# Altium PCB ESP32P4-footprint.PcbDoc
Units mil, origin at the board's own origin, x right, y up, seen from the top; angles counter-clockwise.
Board outline 2834.55 x 2047.04 mil, 2 copper layers (Top Layer, Bottom Layer), stack 65.398 mil thick; 35 components, 0 nets, 396 pads, 0 vias.
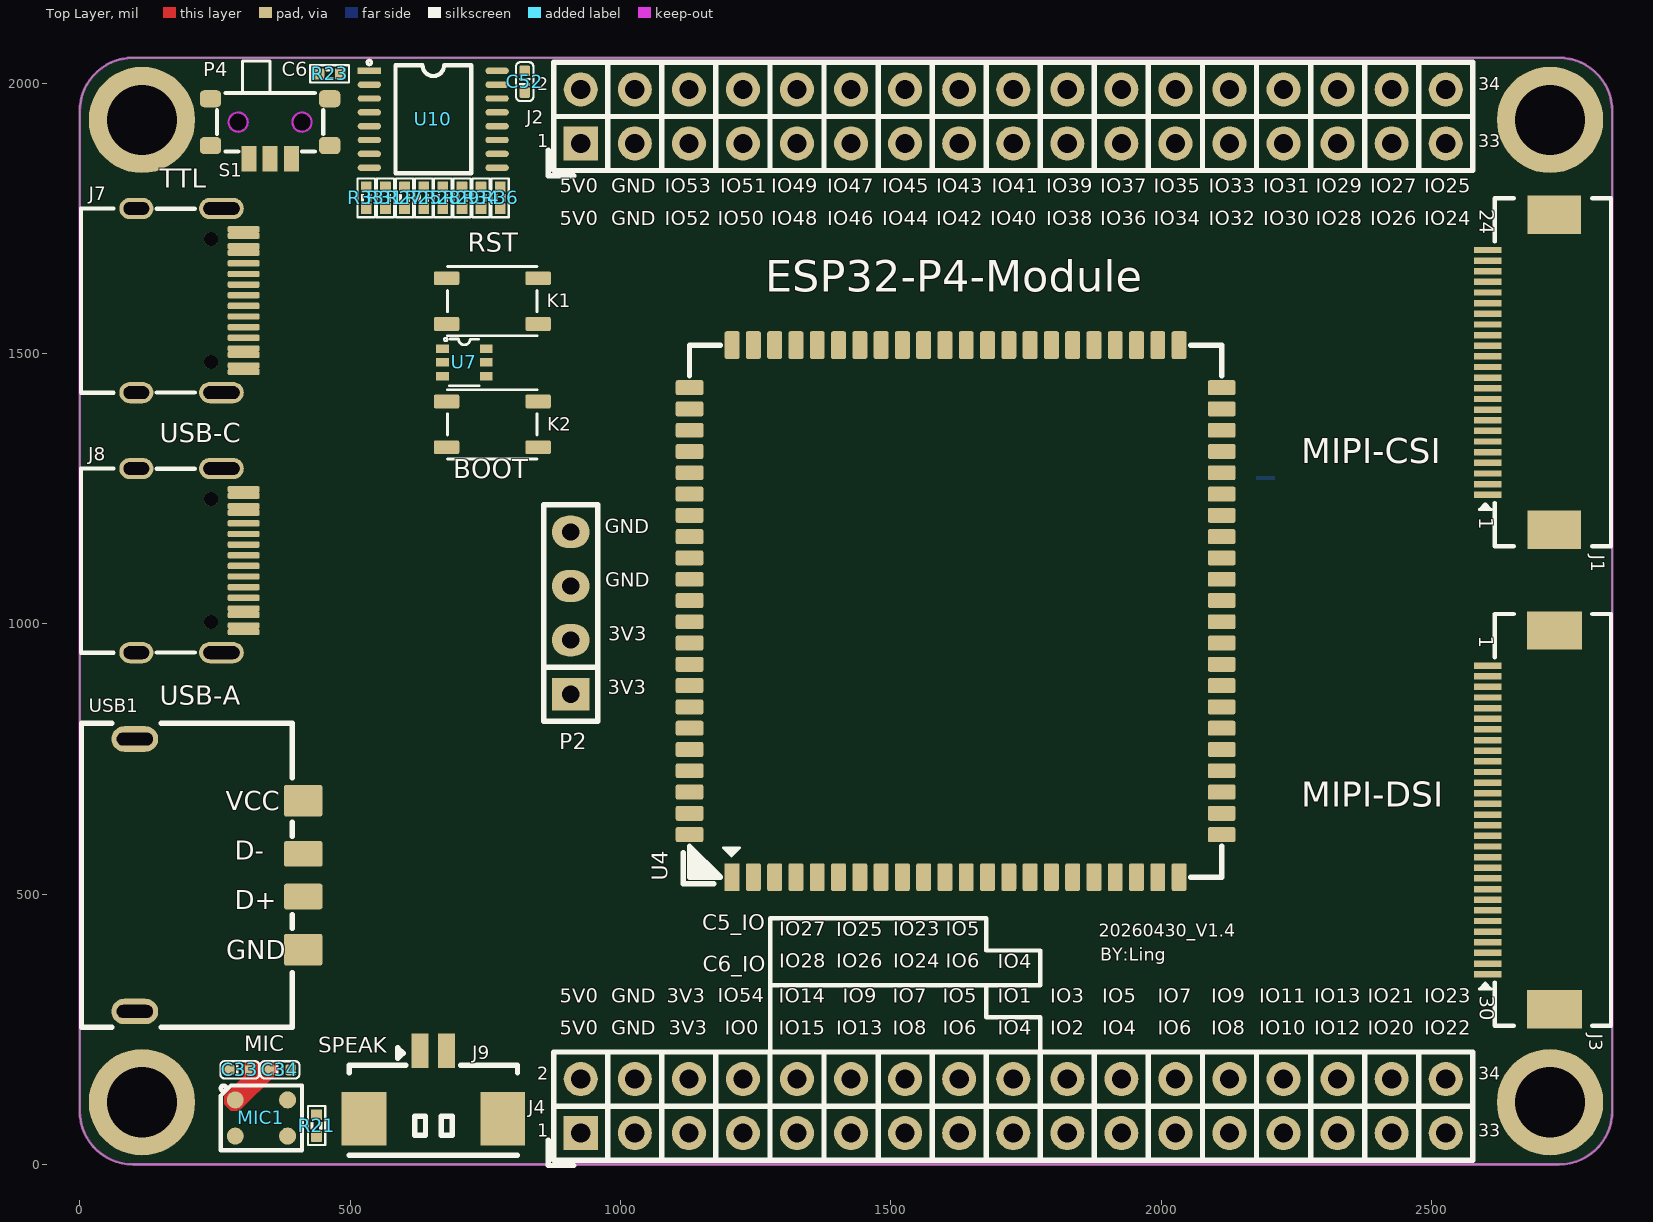
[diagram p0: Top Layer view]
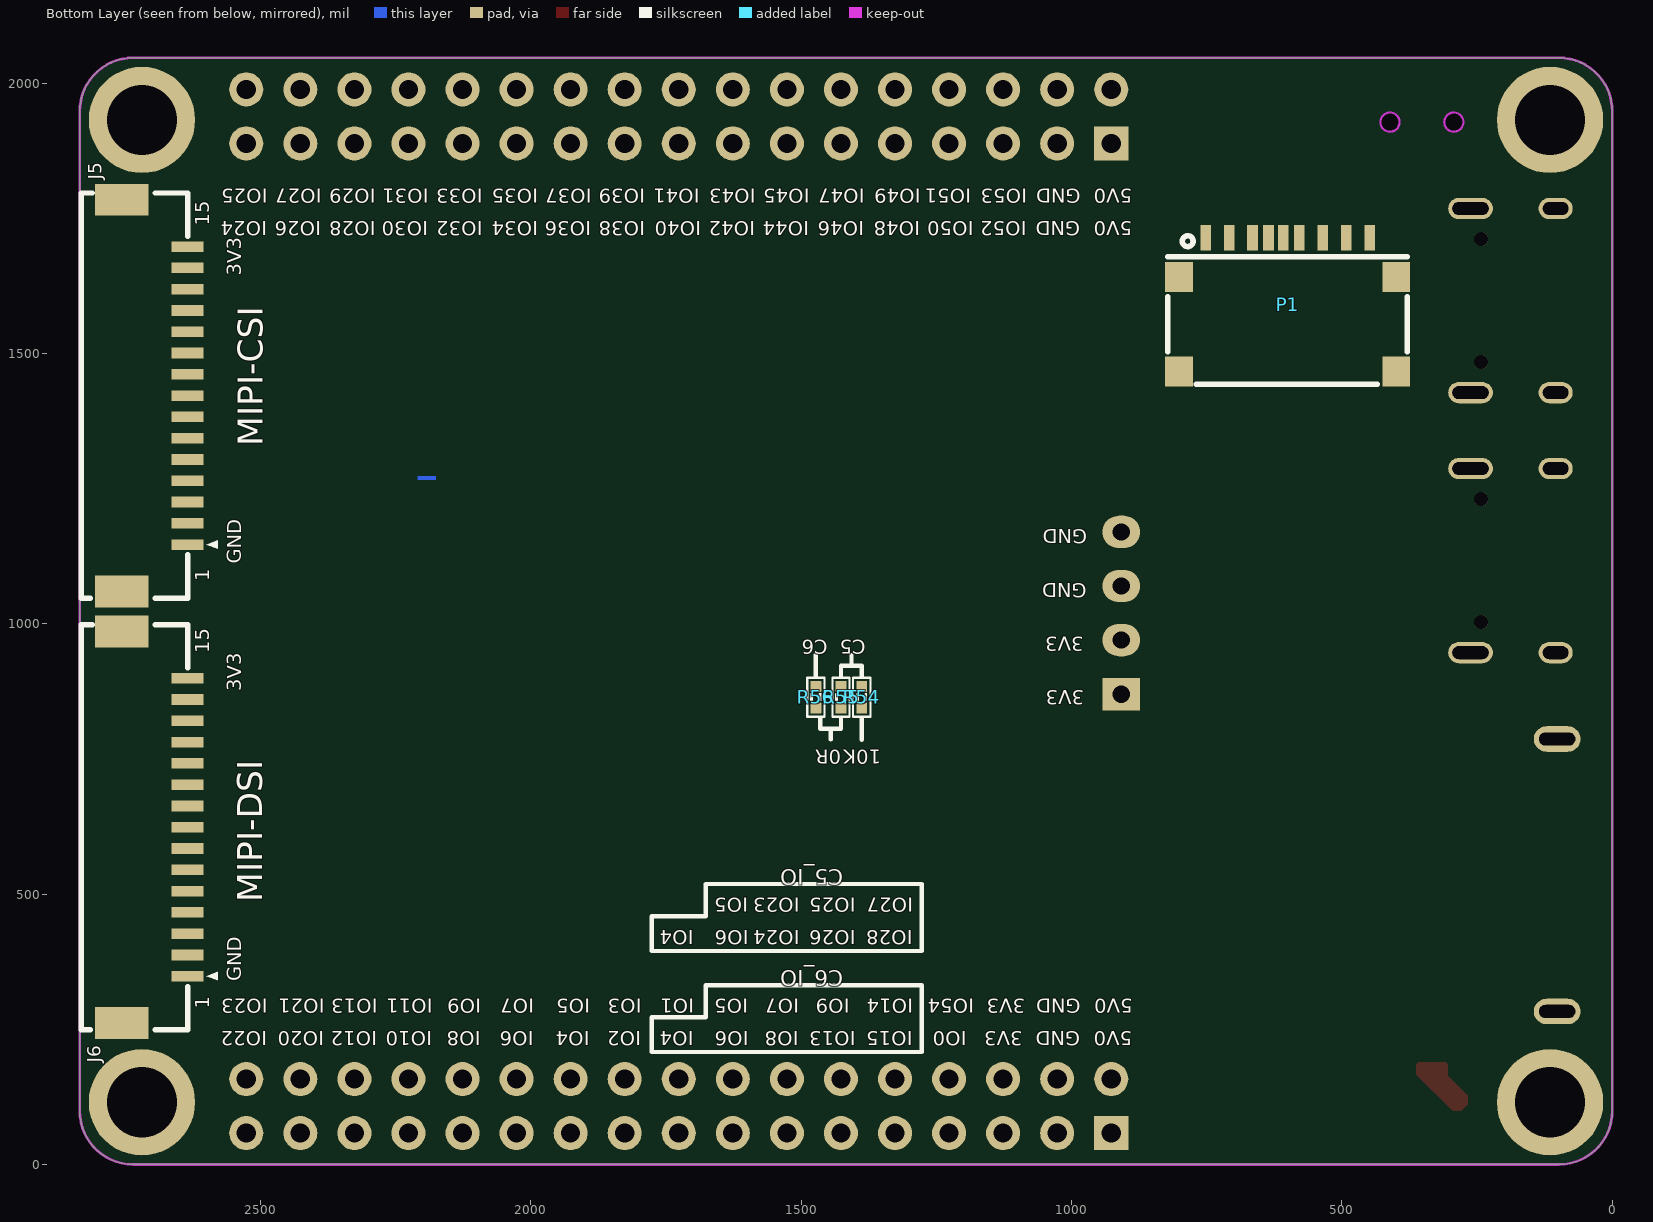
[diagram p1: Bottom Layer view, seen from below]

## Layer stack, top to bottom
Top Solder: solder mask 0.4, Solder Resist, Dk 3.5
Top Layer: signal copper 1.4
Dielectric 1: dielectric 62.5984, FR-4, Dk 4.8
Bottom Layer: signal copper 1.4
Bottom Solder: solder mask 0.4, Solder Resist, Dk 3.5

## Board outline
0,98.43 0,1948.61 cw(c98.42,1948.61) 98.43,2047.04 2736.12,2047.04 cw(c2736.12,1948.61) 2834.55,1948.61 2834.55,98.43 cw(c2736.12,98.43) 2736.12,0 98.43,0 cw(c98.42,98.43)

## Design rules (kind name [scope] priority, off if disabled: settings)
Clearance Clearance_1 [InNamedPolygon('NONET_L-01_P-001') vs InComponent('U4')] p1: gap=6 ignorepadtopadclearanceinfootprint=TRUE except(0: Arc-Hole Track-Hole SMDPad-Hole THPad-Hole Via-Hole Fill-Hole Poly-Hole Region-Hole Text-Hole; 10: SMDPad-Poly)
Clearance [All] p2: gap=6 ignorepadtopadclearanceinfootprint=TRUE except(0: Arc-Hole Track-Hole SMDPad-Hole THPad-Hole Via-Hole Fill-Hole Poly-Hole Region-Hole Text-Hole; 8: THPad-Poly)
ComponentClearance [All] p1: gap=0 collisioncheckmode=3 verticalgap=0 showdistances=FALSE
DiffPairsRouting DIFF100 [All] p1: maxlimit=6 minlimit=6 mostfreqgap=6 toplayer_minwidth=7.4 toplayer_maxwidth=7.4 toplayer_prefwidth=7.4 bottomlayer_minwidth=7.4 bottomlayer_maxwidth=7.4 bottomlayer_prefwidth=7.4 maxuncoupledlength=500
HoleSize [All] p1: absolutevalues=TRUE maxlimit=500 minlimit=1 maxpercent=80.000 minpercent=20.000
HoleToHoleClearance [All] p1: gap=4 allowstackedmicrovias=TRUE
MatchedLengths 15P_DSI [InxSignalClass('15P_DSI')] p1: tolerance=10 checknetsindiffpair=FALSE checkdiffpairvsdiffpair=TRUE checkxsignals=TRUE checkothers=TRUE
MatchedLengths 15P_CSI [InxSignalClass('15P_CSI')] p2: tolerance=10 checknetsindiffpair=FALSE checkdiffpairvsdiffpair=TRUE checkxsignals=TRUE checkothers=TRUE
MatchedLengths DSI [InxSignalClass('DSI')] p3: tolerance=10 checknetsindiffpair=FALSE checkdiffpairvsdiffpair=TRUE checkxsignals=TRUE checkothers=TRUE
MatchedLengths CSI [InxSignalClass('CSI')] p4: tolerance=10 checknetsindiffpair=FALSE checkdiffpairvsdiffpair=TRUE checkxsignals=TRUE checkothers=TRUE
MinimumSolderMaskSliver [All] p1: minsoldermaskwidth=0
PlaneConnect [All] p1: pad.planeconnectstyle=Relief pad.reliefexpansion=20 pad.reliefentries=4 pad.reliefconductorwidth=10 pad.reliefairgap=10 via.planeconnectstyle=Direct via.reliefexpansion=20 via.reliefentries=4 via.reliefconductorwidth=10 via.reliefairgap=10
PolygonConnect [All] p1: thpad.connectstyle=Relief thpad.reliefconductorwidth=15 thpad.reliefentries=4 thpad.polygonreliefangle="90 Angle" thpad.airgapwidth=8 smdpad.connectstyle=Direct smdpad.reliefconductorwidth=15 smdpad.reliefentries=4 smdpad.polygonreliefangle="90 Angle" smdpad.airgapwidth=8 via.connectstyle=Direct via.reliefconductorwidth=10 via.reliefentries=4 via.polygonreliefangle="90 Angle" via.airgapwidth=10
RoutingVias [All] p1: holewidth=28 width=50 viastyle="Through Hole" minholewidth=11 minwidth=18 maxholewidth=28 maxwidth=50
SilkToSilkClearance [All] p1: silktosilkclearance=0
SilkToSolderMaskClearance [IsPad] p1: minsilkscreentomaskgap=0 clearancetoexposedcopper=TRUE
SolderMaskExpansion [All] p1: expansion=4 istentingtop=FALSE
Width [All] p1: maxlimit=50 minlimit=6 preferedwidth=6
22 further rules are at their usual default settings.

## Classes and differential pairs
differential pair USBuart: +USBuart_P -USBuart_N
differential pair USBIN: +USBIN_P -USBIN_N
differential pair USB_D: +USB_D_P -USB_D_N
differential pair USB_A: +USB_A_P -USB_A_N
differential pair DSI_D1: +DSI_D1_P -DSI_D1_N
differential pair DSI_D0: +DSI_D0_P -DSI_D0_N
differential pair DSI_CLK: +DSI_CLK_P -DSI_CLK_N
differential pair CSI_D1: +CSI_D1_P -CSI_D1_N
differential pair CSI_D0: +CSI_D0_P -CSI_D0_N
differential pair CSI_CLK: +CSI_CLK_P -CSI_CLK_N

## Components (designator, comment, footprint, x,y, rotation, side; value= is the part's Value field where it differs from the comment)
C33 "1uF" "CAP_0402 - G" 296,175 r180 top
C34 "0.1uF" "CAP_0402 - G" 370.29,175 r0 top
C52 "0.1uF" "CAP_0402 - G" 823,2003 r270 top
J1 "SC2336" FPC0.5-24P 2702.5,1465.16 r90 top locked
J2 "2X17P排针2.54MM间距" HDR2.54-LI-2x17P 1726.63,1938.52 r0 top locked
J3 "YDP400BT001-V4" FPC0.5-30P 2702.5,637.36 r90 top locked
J4 "2X17P排针2.54MM间距" HDR2.54-LI-2x17P 1726.63,108.01 r0 top locked
J5 "FPC-1.0HF-15PWAR-H20" FPC-SMD_XUNPU_FPC-1.0HF-15PWAR-H20 2696.03,1422.2 r270 bottom locked
J6 "FPC-1.0HF-15PWAR-H20" FPC-SMD_XUNPU_FPC-1.0HF-15PWAR-H20 2696.03,623.78 r270 bottom locked
J7 "TYPEC-16P" TypeC-16P 203.8,1598 r0 top locked
J8 "TYPEC-16P" TypeC-16P 203.8,1117 r0 top locked
J9 "MX1.25-2P" "MX 1.25-LS-2P" 654,155 r0 top locked
K1 "Button-4P" SWITCH_3X4X2.5_4PIN_SMD 763,1597 r180 top
K2 "Button-4P" SWITCH_3X4X2.5_4PIN_SMD 763,1369 r180 top
MIC1 "LMA3729T421-OA1" MIC-SMD_4P-L3.8-W3.0-P2.46-S1.70-TR 336,86 r90 top
P1 "TF-123-ARP9H17" TF-SMD_TF-123-ARP9H15 600.38,1588.31 r0 bottom locked
P2 "1X4排针" "Pin HDR1X4/2.54mm-S" 908,870 r180 top
R21 "0R" "RES_0402 -G" 438,72 r90 top
R23 "10K" "RES_0402 -G" 462.26,2017.35 r180 top
R25 "0R" "RES_0402 -G" 636.08,1788 r90 top
R27 "0R" "RES_0402 -G" 600.71,1788 r90 top
R28 "0R" "RES_0402 -G" 671.45,1788 r270 top
R29 "0R" "RES_0402 -G" 706.82,1788 r270 top
R31 "0R" "RES_0402 -G" 565.34,1788 r90 top
R33 "0R" "RES_0402 -G" 529.97,1788 r270 top
R34 "0R" "RES_0402 -G" 742.19,1788 r270 top
R36 "0R" "RES_0402 -G" 777.56,1788 r270 top
R54 "10K" "RES_0402 -G" 1388,864.22 r90 bottom
R55 "0R" "RES_0402 -G" 1426.46,864.22 r270 bottom
R56 "0R" "RES_0402 -G" 1473,864.22 r270 bottom
S1 "SS-205-AGS7P-150" SS-205-AGS7P-150 352,1928 r180 top
U4 "ESP32-P4C6/C5_Module" ESP32P4模组封装 1620,1023.52 r90 top locked
U7 "DDC114TU-7-F/UMH3N" SC70 711.37,1483.47 r0 top
U10 "RS2233XTSS16-Q1" TSSOP16_N 653.92,1933.35 r0 top
USB1 "10.0 QCHTZB5.7" USB-A-SMD_10.0-QCHTZB5.7 250,535 r0 top locked

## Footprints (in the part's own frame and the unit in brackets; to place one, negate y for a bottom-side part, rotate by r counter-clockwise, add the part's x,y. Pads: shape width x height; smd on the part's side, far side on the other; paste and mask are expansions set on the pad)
"CAP_0402 - G" [mil]
  rrect35% 20x20 smd mask+2: 1(-20,0) 2(20,0)
  silkscreen extent -36,-16 36,16, body extent -20,-10 20,10, height 20
ESP32P4模组封装 [mm]
  rect 1.3x0.7 smd mask+0.051: 1(-12.5,10.5)
  rrect25% 1.3x0.7 smd mask+0.051: 2(-12.5,9.5) 3(-12.5,8.5) 4(-12.5,7.5) 5(-12.5,6.5) 6(-12.5,5.5) 7(-12.5,4.5) 8(-12.5,3.5) 9(-12.5,2.5) 10(-12.5,1.5) 11(-12.5,0.5) 12(-12.5,-0.5) 13(-12.5,-1.5) 14(-12.5,-2.5) 15(-12.5,-3.5) 16(-12.5,-4.5) 17(-12.5,-5.5) 18(-12.5,-6.5) 19(-12.5,-7.5) 20(-12.5,-8.5) 21(-12.5,-9.5) 22(-12.5,-10.5) 45(12.5,-10.5) 46(12.5,-9.5) 47(12.5,-8.5) 48(12.5,-7.5) 49(12.5,-6.5) 50(12.5,-5.5) 51(12.5,-4.5) 52(12.5,-3.5) 53(12.5,-2.5) 54(12.5,-1.5) 55(12.5,-0.5) 56(12.5,0.5) 57(12.5,1.5) 58(12.5,2.5) 59(12.5,3.5) 60(12.5,4.5) 61(12.5,5.5) 62(12.5,6.5) 63(12.5,7.5) 64(12.5,8.5) 65(12.5,9.5) 66(12.5,10.5)
  rrect25% 0.7x1.3 smd mask+0.051: 23(-10.5,-12.5) 24(-9.5,-12.5) 25(-8.5,-12.5) 26(-7.5,-12.5) 27(-6.5,-12.5) 28(-5.5,-12.5) 29(-4.5,-12.5) 30(-3.5,-12.5) 31(-2.5,-12.5) 32(-1.5,-12.5) 33(-0.5,-12.5) 34(0.5,-12.5) 35(1.5,-12.5) 36(2.5,-12.5) 37(3.5,-12.5) 38(4.5,-12.5) 39(5.5,-12.5) 40(6.5,-12.5) 41(7.5,-12.5) 42(8.5,-12.5) 43(9.5,-12.5) 44(10.5,-12.5) 67(10.5,12.5) 68(9.5,12.5) 69(8.5,12.5) 70(7.5,12.5) 71(6.5,12.5) 72(5.5,12.5) 73(4.5,12.5) 74(3.5,12.5) 75(2.5,12.5) 76(1.5,12.5) 77(0.5,12.5) 78(-0.5,12.5) 79(-1.5,12.5) 80(-2.5,12.5) 81(-3.5,12.5) 82(-4.5,12.5) 83(-5.5,12.5) 84(-6.5,12.5) 85(-7.5,12.5) 86(-8.5,12.5) 87(-9.5,12.5) 88(-10.5,12.5)
  silkscreen extent -12.8,-12.5 12.5,12.8, body extent -12.51,-12.51 12.5,12.5, height 3.25
FPC0.5-24P [mm]
  rect 1.8x2.5 smd: 0(-7.4,-0.635) 0(7.4,-0.635)
  rect 0.3x1.3 smd: 1(-5.75,2.497) 2(-5.25,2.497) 3(-4.75,2.497) 4(-4.25,2.497) 5(-3.75,2.497) 6(-3.25,2.497) 7(-2.75,2.497) 8(-2.25,2.497) 9(-1.75,2.497) 10(-1.25,2.497) 11(-0.75,2.497) 12(-0.25,2.497) 13(0.25,2.497) 14(0.75,2.497) 15(1.25,2.497) 16(1.75,2.497) 17(2.25,2.497) 18(2.75,2.497) 19(3.25,2.497) 20(3.75,2.497) 21(4.25,2.497) 22(4.75,2.497) 23(5.25,2.497) 24(5.75,2.497)
  silkscreen extent -8.18,-3.3 8.18,2.89, body extent -8.1,-3.25 8.1,2.75, height 2
FPC0.5-30P [mm]
  rect 1.8x2.58 smd: 0(-8.9,-0.635) 0(8.9,-0.635)
  rect 0.3x1.3 smd: 1(-7.25,2.497) 2(-6.75,2.497) 3(-6.25,2.497) 4(-5.75,2.497) 5(-5.25,2.497) 6(-4.75,2.497) 7(-4.25,2.497) 8(-3.75,2.497) 9(-3.25,2.497) 10(-2.75,2.497) 11(-2.25,2.497) 12(-1.75,2.497) 13(-1.25,2.497) 14(-0.75,2.497) 15(-0.25,2.497) 16(0.25,2.497) 17(0.75,2.497) 18(1.25,2.497) 19(1.75,2.497) 20(2.25,2.497) 21(2.75,2.497) 22(3.25,2.497) 23(3.75,2.497) 24(4.25,2.497) 25(4.75,2.497) 26(5.25,2.497) 27(5.75,2.497) 28(6.25,2.497) 29(6.75,2.497) 30(7.25,2.497)
  silkscreen extent -9.68,-3.3 9.67,2.89, body extent -9.6,-3.2 9.6,2.8, height 2
FPC-SMD_XUNPU_FPC-1.0HF-15PWAR-H20 [mm]
  rect 1.5x2.5 smd paste+0 mask+0.051: 0(-9.2,-1.55) 0(9.2,-1.55)
  rect 0.5x1.5 smd paste+0 mask+0.051: 1(7,1.55) 2(6,1.55) 3(5,1.55) 4(4,1.55) 5(3,1.55) 6(2,1.55) 7(1,1.55) 8(0,1.55) 9(-1,1.55) 10(-2,1.55) 11(-3,1.55) 12(-4,1.55) 13(-5,1.55) 14(-6,1.55) 15(-7,1.55)
  silkscreen extent -9.52,-3.45 9.52,2.97, body extent -9.54,-3.45 9.54,2.45, height 2.02
HDR2.54-LI-2x17P [mm] "双排排针，17x2脚"
  rect 1.6x1.6 hole 0.9: 1(-20.32,-1.27)
  round 1.6 hole 0.9: 2(-20.32,1.27) 3(-17.78,-1.27) 4(-17.78,1.27) 5(-15.24,-1.27) 6(-15.24,1.27) 7(-12.7,-1.27) 8(-12.7,1.27) 9(-10.16,-1.27) 10(-10.16,1.27) 11(-7.62,-1.27) 12(-7.62,1.27) 13(-5.08,-1.27) 14(-5.08,1.27) 15(-2.54,-1.27) 16(-2.54,1.27) 17(0,-1.27) 18(0,1.27) 19(2.54,-1.27) 20(2.54,1.27) 21(5.08,-1.27) 22(5.08,1.27) 23(7.62,-1.27) 24(7.62,1.27) 25(10.16,-1.27) 26(10.16,1.27) 27(12.7,-1.27) 28(12.7,1.27) 29(15.24,-1.27) 30(15.24,1.27) 31(17.78,-1.27) 32(17.78,1.27) 33(20.32,-1.27) 34(20.32,1.27)
  silkscreen extent -21.84,-2.79 21.59,2.54, body extent -21.59,-2.54 21.59,2.54, height 8.5
MIC-SMD_4P-L3.8-W3.0-P2.46-S1.70-TR [mm]
  round 0.8 smd mask+0.051: 1(0.85,1.23) 2(0.85,-1.23) 3(-0.85,-1.23) 4(-0.85,1.23)
  silkscreen extent -1.52,-1.91 1.52,1.9, body extent -1.5,-2 1.5,2, height 0.97
"MX 1.25-LS-2P" [mm] "长：7.25m，宽：3.7mm，高：4.7mm"
  rect 2.1x2.5 smd: 0(-3.255,-1.786) 0(3.255,-1.786)
  rect 0.8x1.6 smd: 1(-0.625,1.405) 2(0.625,1.405)
  silkscreen extent -3.95,-3.51 3.95,1.55, body extent -3.75,-3.51 3.75,1.74, height 3.62
"Pin HDR1X4/2.54mm-S" [mil]
  rect 70x60 hole 32: 1(0,0)
  oval 70x60 hole 32: 2(0,-100) 3(0,-200) 4(0,-300)
  silkscreen extent -50,-350 50,50, body extent -50,-350 50,50, height 336
"RES_0402 -G" [mil]
  rrect10% 20x20 smd mask+2: 1(-20,0) 2(20,0)
  silkscreen extent -36,-16 36,16, body extent -20,-10 20,10, height 14
SC70 [mm]
  rect 0.6x0.4 smd mask+0.025: 1(-1.026,0.65) 2(-1.026,0) 3(-1.026,-0.65) 4(1.026,-0.65) 5(1.026,0) 6(1.026,0.65)
  silkscreen extent -0.95,-1.1 0.7,1.16, body extent -1.2,-1.07 1.2,1.07, height 1.08
SS-205-AGS7P-150 [mm]
  rrect50% 1x0.8 smd mask+0.051: 0(-2.8,-1.1) 0(-2.8,1.1) 0(2.8,-1.1) 0(2.8,1.1)
  rect 0.7x1.2 smd mask+0.051: 1(-1,1.711) 2(0,1.711) 3(1,1.711)
  Keep-Out Layer board cut-out: 1.05,0 1.084,-0.172 1.182,-0.318 1.328,-0.416 1.5,-0.45 1.5,-0.45 1.672,-0.416 1.818,-0.318 1.916,-0.172 1.95,0 1.95,0 1.916,0.172 1.818,0.318 1.672,0.416 1.5,0.45 1.5,0.45 1.328,0.416 1.182,0.318 1.084,0.172 1.05,0
  Keep-Out Layer board cut-out: -1.5,-0.45 -1.672,-0.416 -1.818,-0.318 -1.916,-0.172 -1.95,0 -1.95,0 -1.916,0.172 -1.818,0.318 -1.672,0.416 -1.5,0.45 -1.5,0.45 -1.328,0.416 -1.182,0.318 -1.084,0.172 -1.05,0 -1.05,0 -1.084,-0.172 -1.182,-0.318 -1.328,-0.416 -1.5,-0.45
  Keep-Out Layer circle w0.1: c1.5,0 r0.45
  Keep-Out Layer circle w0.1: c-1.5,0 r0.45
  silkscreen extent -2.5,-2.88 2.5,1.37, body extent -3,-2.82 3,2.18, height 1.38
SWITCH_3X4X2.5_4PIN_SMD [mm]
  rrect25% 1.2x0.65 smd: 1(-2.15,1.075) 2(2.15,1.075) 3(-2.15,-1.075) 4(2.15,-1.075)
  silkscreen extent -2.1,-1.63 2.1,1.63, body extent -2.55,-1.57 2.55,1.57, height 2.5
TF-SMD_TF-123-ARP9H15 [mm]
  rect 1.3x1.4 smd: 0(-5.1,3.092) 0(-5.1,-1.357) 0(5.1,-1.357) 0(5.1,3.092)
  rect 0.5x1.2 smd: 1(3.85,-3.192) 2(2.75,-3.192) 3(1.65,-3.192) 4(0.9,-3.192) 5(-0.55,-3.192) 6(-1.65,-3.192) 7(-2.75,-3.192) 8(-3.85,-3.192) 9(0.2,-3.192)
  silkscreen extent -5.62,-3.29 5.62,3.69, body extent -5.63,-3.41 5.62,3.69, height 1.5
TSSOP16_N [mm] "5*6.4*1mm（长宽高）"
  rect 1.1x0.3 smd mask+0.051: 1(-3.004,2.275)
  oval 1.1x0.3 smd mask+0.051: 2(-3.004,1.625) 3(-3.004,0.975) 4(-3.004,0.325) 5(-3.004,-0.325) 6(-3.004,-0.975) 7(-3.004,-1.625) 8(-3.004,-2.275) 9(2.996,-2.275) 10(2.996,-1.625) 11(2.996,-0.975) 12(2.996,-0.325) 13(2.996,0.325) 14(2.996,0.975) 15(2.996,1.625) 16(2.996,2.275)
  silkscreen extent -3.11,-2.54 1.78,2.77, body extent -3.2,-2.5 3.2,2.5, height 1.03
TypeC-16P [mm]
  round 0.65 hole 0.65: 0(0.98,-2.89) 0(0.98,2.89)
  oval 1.6x1 hole 0.6 slot 1.2 at 0 deg: 1(-2.52,-4.325) 2(-2.52,4.325)
  oval 2.1x1 hole 0.6 slot 1.7 at 0 deg: 3(1.48,4.325) 4(1.48,-4.325)
  rrect50% 1.5x0.3 smd mask+0.051: A1(2.52,3.35) A4(2.52,2.55) A5(2.52,1.25) A6(2.52,0.25) A7(2.52,-0.25) A8(2.52,-1.25) A9(2.52,-2.55) A12(2.52,-3.35) B1(2.52,-3.05) B4(2.52,-2.25) B5(2.52,-1.75) B6(2.52,-0.75) B7(2.52,0.75) B8(2.52,1.75) B9(2.52,2.25) B12(2.52,3.05)
  silkscreen extent -5.12,-4.33 0.22,4.33, body extent -5.18,-4.48 2.57,4.48, height 3.26
USB-A-SMD_10.0-QCHTZB5.7 [mm]
  rrect15% 1.8x1.5 smd paste+0 mask+0.102: 1(4.146,3.5) 4(4.146,-3.5)
  rrect15% 1.8x1.2 smd paste+0 mask+0.102: 2(4.146,1) 3(4.146,-1)
  oval 2.2x1.2 hole 0.61 slot 1.7 at 0 deg: 5(-3.765,-6.4) 6(-3.765,6.4)
  silkscreen extent -6.27,-7.15 3.64,7.15, body extent -6.68,-7.15 4.32,7.15, height 5.8

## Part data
C33 C34 C52: library part CAP, "Capacitor"
J2 J4: library part "Pin HDR2X17"
J3: library part YDP210B001-V9
J5 J6: library part FPC0.5-15P, "贴片"
J7 J8: library part TYPEC-300A-BCP16H130, "16P立式直插TYPEC接口H=13MM，C5454932"
J9 P2: library part "Header 4", "Header, 4-Pin"
K1 K2: "Button"
MIC1: library part MSM381A3729H9CP
P1: "TF-123-ARP9H17,拔插式 MicroSD卡(TF卡) 卡座 短体9P中间侦测 1.7H"
R21 R23 R25 R27 R28 R29 R31 R33 R34 R36 R54 R55 R56: library part Res2, "Resistor"
S1: library part MSK-12C01-07
U4: library part ESP32-P4_Module
U7: library part HUMH9NTN
U10: "2:1(SPDT)4通道模拟开关"
USB1: library part USB-256-BRWH130, "USBA母座无卷边立式直插H=13.1MM，C720542"

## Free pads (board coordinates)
  round 196.85 hole 129.92 mask+0.98: 25(115,115) 25(115,1932.04) 25(2719.55,115) 25(2719.55,1932.04)

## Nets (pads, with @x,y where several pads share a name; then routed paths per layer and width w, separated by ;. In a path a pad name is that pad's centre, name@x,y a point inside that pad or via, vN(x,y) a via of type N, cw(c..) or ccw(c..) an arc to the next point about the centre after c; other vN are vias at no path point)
pads on no net: C33.1 C33.2 C34.1 C34.2 C52.1 C52.2 J1.0 J1.1 J1.2 J1.3 J1.4 J1.5 J1.6 J1.7 J1.8 J1.9 J1.10 J1.11 J1.12 J1.13 J1.14 J1.15 J1.16 J1.17 J1.18 J1.19 J1.20 J1.21 J1.22 J1.23 J1.24 J2.1 J2.2 J2.3 J2.4 J2.5 J2.6 J2.7 J2.8 J2.9 J2.10 J2.11 J2.12 J2.13 J2.14 J2.15 J2.16 J2.17 J2.18 J2.19 J2.20 J2.21 J2.22 J2.23 J2.24 J2.25 J2.26 J2.27 J2.28 J2.29 J2.30 J2.31 J2.32 J2.33 J2.34 J3.0 J3.1 J3.2 J3.3 J3.4 J3.5 J3.6 J3.7 J3.8 J3.9 J3.10 J3.11 J3.12 J3.13 J3.14 J3.15 J3.16 J3.17 J3.18 J3.19 J3.20 J3.21 J3.22 J3.23 J3.24 J3.25 J3.26 J3.27 J3.28 J3.29 J3.30 J4.1 J4.2 J4.3 J4.4 J4.5 J4.6 J4.7 J4.8 J4.9 J4.10 J4.11 J4.12 J4.13 J4.14 J4.15 J4.16 J4.17 J4.18 J4.19 J4.20 J4.21 J4.22 J4.23 J4.24 J4.25 J4.26 J4.27 J4.28 J4.29 J4.30 J4.31 J4.32 J4.33 J4.34 J5.0 J5.1 J5.2 J5.3 J5.4 J5.5 J5.6 J5.7 J5.8 J5.9 J5.10 J5.11 J5.12 J5.13 J5.14 J5.15 J6.0 J6.1 J6.2 J6.3 J6.4 J6.5 J6.6 J6.7 J6.8 J6.9 J6.10 J6.11 J6.12 J6.13 J6.14 J6.15 J7.0 J7.1 J7.2 J7.3 J7.4 J7.A1 J7.A4 J7.A5 J7.A6 J7.A7 J7.A8 J7.A9 J7.A12 J7.B1 J7.B4 J7.B5 J7.B6 J7.B7 J7.B8 J7.B9 J7.B12 J8.0 J8.1 J8.2 J8.3 J8.4 J8.A1 J8.A4 J8.A5 J8.A6 J8.A7 J8.A8 J8.A9 J8.A12 J8.B1 J8.B4 J8.B5 J8.B6 J8.B7 J8.B8 J8.B9 J8.B12 J9.0 J9.1 J9.2 K1.1 K1.2 K1.3 K1.4 K2.1 K2.2 K2.3 K2.4 MIC1.1 MIC1.2 MIC1.3 MIC1.4 P1.0 P1.1 P1.2 P1.3 P1.4 P1.5 P1.6 P1.7 P1.8 P1.9 P2.1 P2.2 P2.3 P2.4 R21.1 R21.2 R23.1 R23.2 R25.1 R25.2 R27.1 R27.2 R28.1 R28.2 R29.1 R29.2 R31.1 R31.2 R33.1 R33.2 R34.1 R34.2 R36.1 R36.2 R54.1 R54.2 R55.1 R55.2 R56.1 R56.2 S1.0 S1.1 S1.2 S1.3 U4.1 U4.2 U4.3 U4.4 U4.5 U4.6 U4.7 U4.8 U4.9 U4.10 U4.11 U4.12 U4.13 U4.14 U4.15 U4.16 U4.17 U4.18 U4.19 U4.20 U4.21 U4.22 U4.23 U4.24 U4.25 U4.26 U4.27 U4.28 U4.29 U4.30 U4.31 U4.32 U4.33 U4.34 U4.35 U4.36 U4.37 U4.38 U4.39 U4.40 U4.41 U4.42 U4.43 U4.44 U4.45 U4.46 U4.47 U4.48 U4.49 U4.50 U4.51 U4.52 U4.53 U4.54 U4.55 U4.56 U4.57 U4.58 U4.59 U4.60 U4.61 U4.62 U4.63 U4.64 U4.65 U4.66 U4.67 U4.68 U4.69 U4.70 U4.71 U4.72 U4.73 U4.74 U4.75 U4.76 U4.77 U4.78 U4.79 U4.80 U4.81 U4.82 U4.83 U4.84 U4.85 U4.86 U4.87 U4.88 U7.1 U7.2 U7.3 U7.4 U7.5 U7.6 U10.1 U10.2 U10.3 U10.4 U10.5 U10.6 U10.7 U10.8 U10.9 U10.10 U10.11 U10.12 U10.13 U10.14 U10.15 U10.16 USB1.1 USB1.2 USB1.3 USB1.4 USB1.5 USB1.6

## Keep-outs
Keep-Out Layer:
  the board outline again, w5

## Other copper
Top Layer:
  pour cut-out: 1190.83,1479.79 1743.63,1479.79 1743.63,1551.5 1191.21,1551.5
  pour cut-out: 1771.81,1479.79 1940.48,1479.79 1940.48,1551.5 1772.19,1551.5
  pour cut-out: 1967.87,1479.79 2058.59,1479.79 2058.59,1551.5 1968.24,1551.5
  pour cut-out: 2076.27,1451.19 2076.27,1293.59 2147.98,1293.59 2147.98,1450.81
  pour cut-out: 2076.27,1265.58 2076.27,1018 2147.98,1018 2147.98,1265.2
  pour cut-out: 2076.27,990.22 2076.27,586.2 2147.98,586.2 2147.98,989.85
  pour cut-out: 2045.96,566.85 1772,566.85 1772,495.15 2045.58,495.15
  pour cut-out: 1744.17,567.25 1300.79,567.25 1300.79,495.54 1743.79,495.54
  pour cut-out: 1163.73,609.95 1163.73,791.55 1092.02,791.55 1092.02,610.32
  pour cut-out: 1092.02,1444.23 1092.02,822.42 1163.73,822.42 1163.73,1443.86
  region: 267,111 279,99 295,99 362,166 362,185.22 358.22,189 308,189 304,185 304,164 267,127
Bottom Layer:
  region: 2209.33,1266.82 2176.33,1266.82 2176.33,1272.55 2209.33,1272.55
  pour cut-out: 2599.47,411.09 2599.47,403.4 2652.55,403.4 2654.83,405.68 2654.83,408.81 2652.55,411.09
  pour cut-out: 2599.47,529.2 2599.47,521.51 2652.55,521.51 2654.83,523.79 2654.83,526.92 2652.55,529.2
  pour cut-out: 2599.47,647.31 2599.47,639.62 2652.55,639.62 2654.83,641.9 2654.83,645.03 2652.55,647.31
  pour cut-out: 2599.47,1209.51 2599.47,1201.82 2652.55,1201.82 2654.83,1204.1 2654.83,1207.23 2652.55,1209.51
  pour cut-out: 2599.47,1327.62 2599.47,1319.93 2652.55,1319.93 2654.83,1322.21 2654.83,1325.34 2652.55,1327.62
  pour cut-out: 2599.47,1445.73 2599.47,1438.04 2652.55,1438.04 2654.83,1440.32 2654.83,1443.45 2652.55,1445.73

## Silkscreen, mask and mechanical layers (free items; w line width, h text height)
Top Overlay:
  lines w8: 1277,208.01 1277,331.7 ; 1776.63,208.01 1776.63,272.16 1677,272.16 1677,331.7 ; 1277,331.7 1277,455.39 1677,455.39 1677,395.85 1776.63,395.85 1776.63,331.7 1677,331.7 ; 1277,331.7 1677,331.7
  text "P4" at 228.45,2003.82 h45
  text "C6" at 373.45,2003.98 h45
  text "TTL" at 148,1794.24 h60
  text "5V0" at 887.33,1788.47 h45
  text "GND" at 982.98,1788.47 h45
  text "IO53" at 1082.15,1788.47 h45
  text "IO51" at 1185.03,1788.47 h45
  text "IO49" at 1278.82,1788.47 h45
  text "IO47" at 1382.65,1788.47 h45
  text "IO45" at 1484.49,1788.47 h45
  text "IO43" at 1584.32,1788.47 h45
  text "IO41" at 1687.15,1788.47 h45
  text "IO39" at 1787.99,1788.47 h45
  text "IO37" at 1887.57,1788.47 h45
  text "IO35" at 1986.07,1788.47 h45
  text "IO33" at 2088.58,1788.47 h45
  text "IO31" at 2189.09,1788.47 h45
  text "IO29" at 2286.6,1788.47 h45
  text "IO27" at 2387.1,1788.47 h45
  text "IO25" at 2486.94,1788.47 h45
  text "24" at 2580.31,1766.97 h45 r270
  text "5V0" at 887.33,1728.02 h45
  text "GND" at 982.98,1728.02 h45
  text "IO52" at 1082.15,1728.02 h45
  text "IO50" at 1180.03,1728.02 h45
  text "IO48" at 1278.82,1728.02 h45
  text "IO46" at 1382.65,1728.02 h45
  text "IO44" at 1484.49,1728.02 h45
  text "IO42" at 1584.32,1728.02 h45
  text "IO40" at 1684.03,1728.02 h45
  text "IO38" at 1787.99,1728.02 h45
  text "IO36" at 1887.57,1728.02 h45
  text "IO34" at 1986.07,1728.02 h45
  text "IO32" at 2088.58,1728.02 h45
  text "IO30" at 2189.09,1728.02 h45
  text "IO28" at 2286.6,1728.02 h45
  text "IO26" at 2387.1,1728.02 h45
  text "IO24" at 2486.94,1728.02 h45
  text "RST" at 718.04,1675.96 h60
  text "ESP32-P4-Module" at 1267.72,1595.08 h100
  text "USB-C" at 148,1323.96 h60
  text "MIPI-CSI" at 2259.48,1280.92 h80
  text "BOOT" at 691.04,1256.96 h60
  text "1" at 2579.82,1197 h45 r270
  text "GND" at 971.03,1158.47 h45
  text "GND" at 971.98,1058.98 h45
  text "1" at 2579.83,978.44 h45 r270
  text "3V3" at 977.95,959.64 h45
  text "3V3" at 977,860.31 h45
  text "USB-A" at 148,837.96 h60
  text "MIPI-DSI" at 2259.48,645.92 h80
  text "C5_IO" at 1151.59,423.16 h50
  text "IO27" at 1293.53,413.43 h45
  text "IO25" at 1399.2,413.15 h45
  text "IO23" at 1504.25,413.43 h45
  text "IO5" at 1601.36,413.43 h45
  text "20260430_V1.4" at 1884.55,412.43 h40
  text "BY:Ling" at 1887.55,368.07 h40
  text "IO28" at 1293.53,354.16 h45
  text "IO26" at 1399.2,354.16 h45
  text "IO24" at 1504.25,354.16 h45
  text "IO6" at 1601.36,354.16 h45
  text "IO4" at 1698.4,354.15 h45
  text "C6_IO" at 1152.03,346.4 h50
  text "30" at 2580.3,312 h45 r270
  text "5V0" at 887.33,289.74 h45
  text "GND" at 982.98,289.74 h45
  text "3V3" at 1086.12,289.59 h45
  text "IO54" at 1180.03,290.47 h45
  text "IO14" at 1293.16,289.74 h45
  text "IO7" at 1503.88,289.74 h45
  text "IO5" at 1595.99,289.74 h45
  text "IO1" at 1698.03,289.74 h45
  text "IO3" at 1795.43,289.74 h45
  text "IO5" at 1890.82,289.74 h45
  text "IO7" at 1993.82,289.74 h45
  text "IO9" at 2092.57,289.74 h45
  text "IO11" at 2181.67,289.74 h45
  text "IO13" at 2283.86,289.74 h45
  text "IO21" at 2381.95,289.74 h45
  text "IO23" at 2486.94,289.74 h45
  text "IO9" at 1411.03,289.47 h45
  text "5V0" at 887.33,230.3 h45
  text "GND" at 982.98,230.47 h45
  text "3V3" at 1089.14,230.32 h45
  text "IO0" at 1193.03,230.47 h45
  text "IO15" at 1293.16,230.47 h45
  text "IO13" at 1398.83,230.47 h45
  text "IO8" at 1503.88,230.47 h45
  text "IO6" at 1595.99,230.47 h45
  text "IO4" at 1698.03,230.47 h45
  text "IO2" at 1795.43,230.47 h45
  text "IO4" at 1890.82,230.47 h45
  text "IO6" at 1993.82,230.47 h45
  text "IO8" at 2092.57,230.47 h45
  text "IO10" at 2181.67,230.47 h45
  text "IO12" at 2283.86,230.47 h45
  text "IO20" at 2381.95,230.47 h45
  text "IO22" at 2487.17,230.47 h45
  text "MIC" at 304.06,198.9 h50
  text "SPEAK" at 441.48,196.76 h50
Bottom Overlay:
  lines w8: 1388,785.43 1388,826.22 ; 1388,902.22 1388,922.22 1426.46,922.22 1426.46,902.22 ; 1407.23,922.22 1407.23,942.22 ; 1426.46,826.22 1426.46,806.22 1464.93,806.22 1464.93,826.22 ; 1445.69,786.22 1445.69,806.22 ; 1473,902.22 1473,943 ; 1277,208.01 1776.63,208.01 1776.63,272.16 1677,272.16 1677,331.7 1277,331.7 1277,208.01 ; 1277,395 1277,518.69 1677,518.69 1677,459.15 1776.63,459.15 1776.63,395 1277,395
  text "5V0" at 887.57,1814.11 h45 r180
  text "GND" at 983.22,1813.96 h45 r180
  text "IO53" at 1082.4,1814.11 h45 r180
  text "IO51" at 1185.27,1814.11 h45 r180
  text "IO49" at 1279.06,1814.11 h45 r180
  text "IO47" at 1382.9,1814.11 h45 r180
  text "IO45" at 1484.73,1814.11 h45 r180
  text "IO43" at 1584.56,1814.11 h45 r180
  text "IO41" at 1687.39,1814.11 h45 r180
  text "IO39" at 1788.23,1814.11 h45 r180
  text "IO37" at 1887.81,1814.11 h45 r180
  text "IO35" at 1986.31,1814.11 h45 r180
  text "IO33" at 2088.82,1814.11 h45 r180
  text "IO31" at 2189.33,1814.11 h45 r180
  text "IO29" at 2286.84,1814.11 h45 r180
  text "IO27" at 2387.35,1814.11 h45 r180
  text "IO25" at 2487.18,1814.11 h45 r180
  text "5V0" at 888.07,1753.67 h45 r180
  text "IO52" at 1082.9,1753.67 h45 r180
  text "IO50" at 1180.77,1753.67 h45 r180
  text "IO48" at 1279.56,1753.67 h45 r180
  text "IO46" at 1383.4,1753.67 h45 r180
  text "IO44" at 1485.23,1753.67 h45 r180
  text "IO42" at 1585.06,1753.67 h45 r180
  text "IO40" at 1684.77,1753.67 h45 r180
  text "IO38" at 1788.73,1753.67 h45 r180
  text "IO36" at 1888.31,1753.67 h45 r180
  text "IO34" at 1986.81,1753.67 h45 r180
  text "IO32" at 2089.32,1753.67 h45 r180
  text "IO30" at 2189.83,1753.67 h45 r180
  text "IO28" at 2287.34,1753.67 h45 r180
  text "IO26" at 2387.85,1753.67 h45 r180
  text "IO24" at 2487.68,1753.67 h45 r180
  text "GND" at 983.72,1753.51 h45 r180
  text "15" at 2586.31,1736.42 h45 r270
  text "3V3" at 2526.31,1644 h45 r270
  text "MIPI-CSI" at 2480.61,1328.06 h80 r270
  text "GND" at 971.03,1183.96 h45 r180
  text "GND" at 2526.47,1111.03 h45 r270
  text "GND" at 971.98,1084.47 h45 r180
  text "1" at 2586.31,1078.42 h45 r270
  text "3V3" at 977.95,985.29 h45 r180
  text "C5" at 1381.03,979.53 h45 r180
  text "C6" at 1451.03,979.69 h45 r180
  text "15" at 2586.31,946 h45 r270
  text "3V3" at 977,885.96 h45 r180
  text "3V3" at 2526.31,875.58 h45 r270
  text "10K" at 1352,776.53 h45 r180
  text "0R" at 1426,776.53 h45 r180
  text "C5_IO" at 1422.03,556.58 h50 r180
  text "IO27" at 1292.9,502.38 h45 r180
  text "IO25" at 1399.57,502.38 h45 r180
  text "IO23" at 1502.62,502.38 h45 r180
  text "IO5" at 1598.32,502.38 h45 r180
  text "MIPI-DSI" at 2481.61,485.06 h80 r270
  text "IO28" at 1293.9,442.93 h45 r180
  text "IO26" at 1399.57,442.93 h45 r180
  text "IO24" at 1502.62,442.93 h45 r180
  text "IO6" at 1596.73,442.93 h45 r180
  text "IO4" at 1698.77,442.93 h45 r180
  text "C6_IO" at 1422.03,369.6 h50 r180
  text "GND" at 2526.47,338.61 h45 r270
  text "3V3" at 1085.86,315.55 h45 r180
  text "5V0" at 887.07,315.39 h45 r180
  text "GND" at 982.72,315.39 h45 r180
  text "IO54" at 1179.77,315.39 h45 r180
  text "IO14" at 1292.9,315.39 h45 r180
  text "IO9" at 1410.77,315.39 h45 r180
  text "IO7" at 1503.62,315.39 h45 r180
  text "IO5" at 1598.32,315.39 h45 r180
  text "IO1" at 1697.77,315.39 h45 r180
  text "IO3" at 1795.17,315.39 h45 r180
  text "IO5" at 1890.56,315.39 h45 r180
  text "IO7" at 1993.56,315.39 h45 r180
  text "IO9" at 2092.31,315.39 h45 r180
  text "IO11" at 2181.41,315.39 h45 r180
  text "IO13" at 2283.6,315.39 h45 r180
  text "IO21" at 2381.69,315.39 h45 r180
  text "IO23" at 2486.68,315.39 h45 r180
  text "1" at 2586.31,288 h45 r270
  text "5V0" at 888.07,255.95 h45 r180
  text "GND" at 983.72,255.79 h45 r180
  text "3V3" at 1089.89,255.79 h45 r180
  text "IO0" at 1193.77,255.95 h45 r180
  text "IO15" at 1293.9,255.95 h45 r180
  text "IO13" at 1399.57,255.95 h45 r180
  text "IO8" at 1504.62,255.95 h45 r180
  text "IO6" at 1596.73,255.95 h45 r180
  text "IO4" at 1698.77,255.95 h45 r180
  text "IO2" at 1796.17,255.95 h45 r180
  text "IO4" at 1891.56,255.95 h45 r180
  text "IO6" at 1994.56,255.95 h45 r180
  text "IO8" at 2093.31,255.95 h45 r180
  text "IO10" at 2182.41,255.95 h45 r180
  text "IO12" at 2284.6,255.95 h45 r180
  text "IO20" at 2382.69,255.95 h45 r180
  text "IO22" at 2487.91,255.95 h45 r180

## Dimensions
115,115 to 2719.55,115 on Top Overlay
115,1932.04 to 115,115 on Top Overlay
2736.12,0 to 2736.12,2047.04 on Top Overlay
0,1948.61 to 2834.55,1948.61 on Top Overlay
